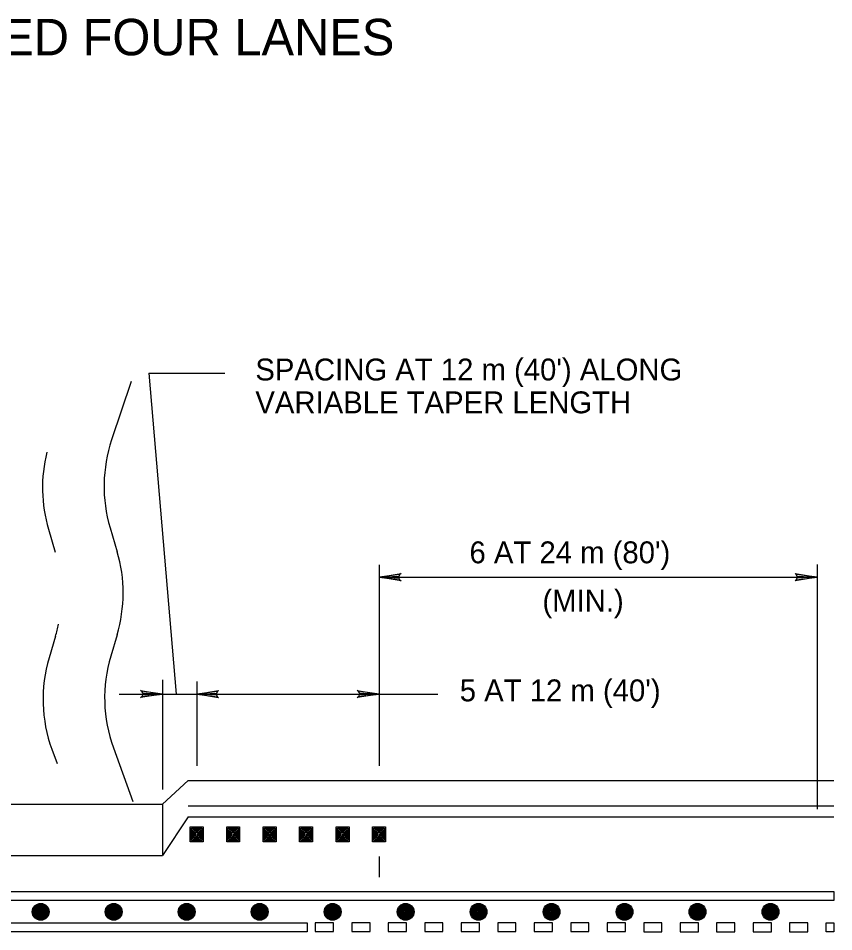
# Model space of a CAD drawing. Extents: x 639362 to 641108, y 298458 to 299646.
# Drawn here: x 640689.2 to 640800.9, y 299355.1 to 299480.3 of the extents above; entities that cross this region are included whole.
import ezdxf

# ---------------------------------------------------------------- set-up
doc = ezdxf.new("R2010")
doc.units = 0
doc.layers.add('2', color=7, linetype='Continuous')
doc.layers.add('3', color=7, linetype='Continuous')

# ---------------------------------------------------------------- blocks, each defined once
blk = doc.blocks.new('RARROW')
at = {"layer": '3'}
blk.add_lwpolyline([(-2.2695, 0.285), (-2.184875, 0.12075), (0, 0), (-2.2695, 0.285), (-2.38575, 0.384625), (0, 0), (-2.183125, -0.108), (-2.262875, -0.2705), (0, 0), (-2.38575, -0.379125), (-2.262875, -0.2705)], dxfattribs=at)

msp = doc.modelspace()

# ---------------------------------------------------------------- linework, layer by layer
at = {"layer": '2'}
for p, q in [((640707.1, 299431.65), (640710.82, 299387.69)), ((640707.1, 299431.65), (640717.52, 299431.65)), ((640704.67, 299430.52), (640701.99, 299422.54)), ((640693.33, 299410.27), (640694.26, 299407.14)), ((640701.77, 299410.48), (640702.75, 299407.2)), ((640738.64, 299405.38), (640738.64, 299377.85)), ((640798.64, 299405.43), (640798.64, 299371.92)), ((640738.64, 299403.7), (640798.64, 299403.7)), ((640702.74, 299395.81), (640701.86, 299392.88)), ((640694.3, 299395.6), (640693.42, 299392.66)), ((640708.95, 299389.65), (640708.95, 299374.61)), ((640713.64, 299389.43), (640713.64, 299377.85)), ((640703, 299387.69), (640713.64, 299387.69)), ((640713.64, 299387.69), (640746.68, 299387.69)), ((640693.79, 299380.12), (640694.51, 299378.15)), ((640702.24, 299380.33), (640704.91, 299372.97)), ((640712.47, 299375.85), (640708.95, 299372.61)), ((640712.47, 299375.85), (640800.93, 299375.85)), ((640671.45, 299372.61), (640708.95, 299372.61)), ((640708.95, 299372.61), (640708.95, 299365.58)), ((640712.47, 299372.35), (640800.93, 299372.35)), ((640712.47, 299370.85), (640708.95, 299365.58)), ((640712.47, 299370.85), (640800.93, 299370.85)), ((640712.75, 299369.47), (640714.53, 299369.47)), ((640712.75, 299367.43), (640712.75, 299369.47)), ((640714.53, 299369.47), (640714.53, 299367.43)), ((640717.75, 299369.47), (640719.53, 299369.47)), ((640717.75, 299367.43), (640717.75, 299369.47)), ((640719.53, 299369.47), (640719.53, 299367.43)), ((640722.75, 299369.47), (640724.53, 299369.47)), ((640722.75, 299367.43), (640722.75, 299369.47)), ((640724.53, 299369.47), (640724.53, 299367.43)), ((640727.75, 299369.47), (640729.53, 299369.47)), ((640727.75, 299367.43), (640727.75, 299369.47)), ((640729.53, 299369.47), (640729.53, 299367.43)), ((640732.75, 299369.47), (640734.53, 299369.47)), ((640732.75, 299367.43), (640732.75, 299369.47)), ((640734.53, 299369.47), (640734.53, 299367.43)), ((640737.75, 299369.47), (640739.53, 299369.47)), ((640737.75, 299367.43), (640737.75, 299369.47)), ((640739.53, 299369.47), (640739.53, 299367.43)), ((640712.93, 299369.29), (640714.35, 299369.29)), ((640712.93, 299367.61), (640712.93, 299369.29)), ((640713.11, 299369.12), (640714.17, 299369.12)), ((640713.11, 299367.79), (640713.11, 299369.12)), ((640713.28, 299367.96), (640713.28, 299368.94)), ((640713.28, 299368.94), (640713.99, 299368.94)), ((640713.46, 299368.76), (640713.82, 299368.76)), ((640713.46, 299368.14), (640713.46, 299368.76)), ((640713.82, 299368.14), (640713.46, 299368.14)), ((640713.64, 299368.59), (640713.64, 299368.32)), ((640713.82, 299368.76), (640713.82, 299368.14)), ((640713.99, 299368.94), (640713.99, 299367.96)), ((640714.17, 299369.12), (640714.17, 299367.79)), ((640714.35, 299369.29), (640714.35, 299367.61)), ((640717.93, 299369.29), (640719.35, 299369.29)), ((640717.93, 299367.61), (640717.93, 299369.29)), ((640718.11, 299369.11), (640719.17, 299369.11)), ((640718.11, 299367.79), (640718.11, 299369.11)), ((640718.28, 299367.96), (640718.28, 299368.94)), ((640718.28, 299368.94), (640718.99, 299368.94)), ((640718.46, 299368.76), (640718.82, 299368.76)), ((640718.46, 299368.14), (640718.46, 299368.76)), ((640718.82, 299368.14), (640718.46, 299368.14)), ((640718.64, 299368.59), (640718.64, 299368.32)), ((640718.82, 299368.76), (640718.82, 299368.14)), ((640718.99, 299368.94), (640718.99, 299367.96)), ((640719.17, 299369.11), (640719.17, 299367.79)), ((640719.35, 299369.29), (640719.35, 299367.61)), ((640722.93, 299369.29), (640724.35, 299369.29)), ((640722.93, 299367.61), (640722.93, 299369.29)), ((640723.11, 299369.11), (640724.17, 299369.11)), ((640723.11, 299367.79), (640723.11, 299369.11)), ((640723.28, 299367.96), (640723.28, 299368.94)), ((640723.28, 299368.94), (640723.99, 299368.94)), ((640723.46, 299368.76), (640723.82, 299368.76)), ((640723.46, 299368.14), (640723.46, 299368.76)), ((640723.82, 299368.14), (640723.46, 299368.14)), ((640723.64, 299368.58), (640723.64, 299368.32)), ((640723.82, 299368.76), (640723.82, 299368.14)), ((640723.99, 299368.94), (640723.99, 299367.96)), ((640724.17, 299369.11), (640724.17, 299367.79)), ((640724.35, 299369.29), (640724.35, 299367.61)), ((640727.93, 299369.29), (640729.35, 299369.29)), ((640727.93, 299367.61), (640727.93, 299369.29)), ((640728.11, 299369.11), (640729.17, 299369.11)), ((640728.11, 299367.78), (640728.11, 299369.11)), ((640728.28, 299367.96), (640728.28, 299368.94)), ((640728.28, 299368.94), (640728.99, 299368.94)), ((640728.46, 299368.76), (640728.82, 299368.76)), ((640728.46, 299368.14), (640728.46, 299368.76)), ((640728.64, 299368.58), (640728.64, 299368.31)), ((640728.82, 299368.76), (640728.82, 299368.14)), ((640728.99, 299368.94), (640728.99, 299367.96)), ((640729.17, 299369.11), (640729.17, 299367.78)), ((640729.35, 299369.29), (640729.35, 299367.61)), ((640732.93, 299369.29), (640734.35, 299369.29)), ((640732.93, 299367.6), (640732.93, 299369.29)), ((640733.11, 299369.11), (640734.17, 299369.11)), ((640733.11, 299367.78), (640733.11, 299369.11)), ((640733.28, 299367.96), (640733.28, 299368.93)), ((640733.28, 299368.93), (640733.99, 299368.93)), ((640733.46, 299368.76), (640733.82, 299368.76)), ((640733.46, 299368.14), (640733.46, 299368.76)), ((640733.64, 299368.58), (640733.64, 299368.31)), ((640733.82, 299368.76), (640733.82, 299368.14)), ((640733.99, 299368.93), (640733.99, 299367.96)), ((640734.17, 299369.11), (640734.17, 299367.78)), ((640734.35, 299369.29), (640734.35, 299367.6)), ((640737.93, 299369.29), (640739.35, 299369.29)), ((640737.93, 299367.6), (640737.93, 299369.29)), ((640738.11, 299369.11), (640739.17, 299369.11)), ((640738.11, 299367.78), (640738.11, 299369.11)), ((640738.28, 299367.96), (640738.28, 299368.93)), ((640738.28, 299368.93), (640738.99, 299368.93)), ((640738.46, 299368.76), (640738.82, 299368.76)), ((640738.46, 299368.14), (640738.46, 299368.76)), ((640738.64, 299368.58), (640738.64, 299368.31)), ((640738.82, 299368.76), (640738.82, 299368.14)), ((640738.99, 299368.93), (640738.99, 299367.96)), ((640739.17, 299369.11), (640739.17, 299367.78)), ((640739.35, 299369.29), (640739.35, 299367.6)), ((640714.53, 299367.43), (640712.75, 299367.43)), ((640714.35, 299367.61), (640712.93, 299367.61)), ((640714.17, 299367.79), (640713.11, 299367.79)), ((640713.99, 299367.96), (640713.28, 299367.96)), ((640719.53, 299367.43), (640717.75, 299367.43)), ((640719.35, 299367.61), (640717.93, 299367.61)), ((640719.17, 299367.79), (640718.11, 299367.79)), ((640718.99, 299367.96), (640718.28, 299367.96)), ((640724.53, 299367.43), (640722.75, 299367.43)), ((640724.35, 299367.61), (640722.93, 299367.61)), ((640724.17, 299367.79), (640723.11, 299367.79)), ((640723.99, 299367.96), (640723.28, 299367.96)), ((640729.53, 299367.43), (640727.75, 299367.43)), ((640729.35, 299367.61), (640727.93, 299367.61)), ((640729.17, 299367.78), (640728.11, 299367.78)), ((640728.99, 299367.96), (640728.28, 299367.96)), ((640728.82, 299368.14), (640728.46, 299368.14)), ((640734.53, 299367.43), (640732.75, 299367.43)), ((640734.35, 299367.6), (640732.93, 299367.6)), ((640734.17, 299367.78), (640733.11, 299367.78)), ((640733.99, 299367.96), (640733.28, 299367.96)), ((640733.82, 299368.14), (640733.46, 299368.14)), ((640739.53, 299367.43), (640737.75, 299367.43)), ((640739.35, 299367.6), (640737.93, 299367.6)), ((640739.17, 299367.78), (640738.11, 299367.78)), ((640738.99, 299367.96), (640738.28, 299367.96)), ((640738.82, 299368.14), (640738.46, 299368.14)), ((640671.45, 299365.58), (640708.95, 299365.58)), ((640738.64, 299365.43), (640738.64, 299362.61)), ((640652.18, 299360.61), (640800.93, 299360.61)), ((640800.93, 299359.41), (640652.18, 299359.41)), ((640800.93, 299360.61), (640800.93, 299359.41)), ((640577.73, 299356.31), (640728.77, 299356.31)), ((640728.77, 299356.31), (640728.77, 299355.11)), ((640729.89, 299356.33), (640729.89, 299355.13)), ((640732.39, 299356.33), (640729.89, 299356.33)), ((640732.39, 299355.13), (640732.39, 299356.33)), ((640734.89, 299356.33), (640734.89, 299355.13)), ((640737.39, 299356.33), (640734.89, 299356.33)), ((640737.39, 299355.13), (640737.39, 299356.33)), ((640739.89, 299356.32), (640739.89, 299355.12)), ((640742.39, 299356.32), (640739.89, 299356.32)), ((640742.39, 299355.12), (640742.39, 299356.32)), ((640744.89, 299356.32), (640744.89, 299355.12)), ((640747.39, 299356.32), (640744.89, 299356.32)), ((640747.39, 299355.12), (640747.39, 299356.32)), ((640749.89, 299356.32), (640749.89, 299355.12)), ((640752.39, 299356.32), (640749.89, 299356.32)), ((640752.39, 299355.12), (640752.39, 299356.32)), ((640754.89, 299356.32), (640754.89, 299355.12)), ((640757.39, 299356.32), (640754.89, 299356.32)), ((640757.39, 299355.12), (640757.39, 299356.32)), ((640759.89, 299356.32), (640759.89, 299355.12)), ((640762.39, 299356.32), (640759.89, 299356.32)), ((640762.39, 299355.12), (640762.39, 299356.32)), ((640764.89, 299356.32), (640764.89, 299355.12)), ((640767.39, 299356.32), (640764.89, 299356.32)), ((640767.39, 299355.12), (640767.39, 299356.32)), ((640769.89, 299356.32), (640769.89, 299355.12)), ((640772.39, 299356.32), (640769.89, 299356.32)), ((640772.39, 299355.12), (640772.39, 299356.32)), ((640774.89, 299356.32), (640774.89, 299355.11)), ((640777.39, 299356.32), (640774.89, 299356.32)), ((640777.39, 299355.11), (640777.39, 299356.32)), ((640779.89, 299356.31), (640779.89, 299355.11)), ((640782.39, 299356.31), (640779.89, 299356.31)), ((640782.39, 299355.11), (640782.39, 299356.31)), ((640784.89, 299356.31), (640784.89, 299355.11)), ((640787.39, 299356.31), (640784.89, 299356.31)), ((640787.39, 299355.11), (640787.39, 299356.31)), ((640789.89, 299356.31), (640789.89, 299355.11)), ((640792.39, 299356.31), (640789.89, 299356.31)), ((640792.39, 299355.11), (640792.39, 299356.31)), ((640794.89, 299356.31), (640794.89, 299355.11)), ((640797.39, 299356.31), (640794.89, 299356.31)), ((640797.39, 299355.11), (640797.39, 299356.31)), ((640799.89, 299355.11), (640799.89, 299356.31)), ((640799.89, 299356.31), (640800.93, 299356.31)), ((640800.93, 299356.31), (640800.93, 299355.11)), ((640728.77, 299355.11), (640577.73, 299355.11)), ((640729.89, 299355.13), (640732.39, 299355.13)), ((640734.89, 299355.12), (640737.39, 299355.12)), ((640739.89, 299355.12), (640742.39, 299355.12)), ((640744.89, 299355.12), (640747.39, 299355.12)), ((640749.89, 299355.12), (640752.39, 299355.12)), ((640754.89, 299355.12), (640757.39, 299355.12)), ((640759.89, 299355.12), (640762.39, 299355.12)), ((640764.89, 299355.12), (640767.39, 299355.12)), ((640769.89, 299355.12), (640772.39, 299355.12)), ((640774.89, 299355.11), (640777.39, 299355.11)), ((640779.89, 299355.11), (640782.39, 299355.11)), ((640784.89, 299355.11), (640787.39, 299355.11)), ((640789.89, 299355.11), (640792.39, 299355.11)), ((640794.89, 299355.11), (640797.39, 299355.11)), ((640800.93, 299355.11), (640799.89, 299355.11)), ((640799.89, 299355.11), (640799.89, 299355.11))]:
    msp.add_line(p, q, dxfattribs=at)
for centre, radius in [((640692.27, 299357.84), 1.15), ((640692.27, 299357.84), 1.07), ((640692.27, 299357.84), 0.985), ((640692.27, 299357.84), 0.904), ((640692.27, 299357.84), 0.822), ((640692.27, 299357.84), 0.741), ((640692.27, 299357.84), 0.659), ((640692.27, 299357.84), 0.578), ((640692.27, 299357.84), 0.496), ((640692.27, 299357.84), 0.414), ((640692.27, 299357.84), 0.333), ((640702.27, 299357.84), 1.15), ((640702.27, 299357.84), 1.07), ((640702.27, 299357.84), 0.985), ((640702.27, 299357.84), 0.904), ((640702.27, 299357.84), 0.822), ((640702.27, 299357.84), 0.741), ((640702.27, 299357.84), 0.659), ((640702.27, 299357.84), 0.578), ((640702.27, 299357.84), 0.496), ((640702.27, 299357.84), 0.414), ((640702.27, 299357.84), 0.333), ((640712.27, 299357.83), 1.15), ((640712.27, 299357.83), 1.07), ((640712.27, 299357.83), 0.985), ((640712.27, 299357.83), 0.904), ((640712.27, 299357.83), 0.822), ((640712.27, 299357.83), 0.741), ((640712.27, 299357.83), 0.659), ((640712.27, 299357.83), 0.578), ((640712.27, 299357.83), 0.496), ((640712.27, 299357.83), 0.414), ((640712.27, 299357.83), 0.333), ((640722.27, 299357.83), 1.15), ((640722.27, 299357.83), 1.07), ((640722.27, 299357.83), 0.985), ((640722.27, 299357.83), 0.904), ((640722.27, 299357.83), 0.822), ((640722.27, 299357.83), 0.741), ((640722.27, 299357.83), 0.659), ((640722.27, 299357.83), 0.578), ((640722.27, 299357.83), 0.496), ((640722.27, 299357.83), 0.414), ((640722.27, 299357.83), 0.333), ((640732.27, 299357.83), 1.15), ((640732.27, 299357.83), 1.07), ((640732.27, 299357.83), 0.985), ((640732.27, 299357.83), 0.904), ((640732.27, 299357.83), 0.822), ((640732.27, 299357.83), 0.741), ((640732.27, 299357.83), 0.659), ((640732.27, 299357.83), 0.578), ((640732.27, 299357.83), 0.496), ((640732.27, 299357.83), 0.414), ((640732.27, 299357.83), 0.333), ((640742.27, 299357.83), 1.15), ((640742.27, 299357.83), 1.07), ((640742.27, 299357.83), 0.985), ((640742.27, 299357.83), 0.904), ((640742.27, 299357.83), 0.822), ((640742.27, 299357.83), 0.741), ((640742.27, 299357.83), 0.659), ((640742.27, 299357.83), 0.578), ((640742.27, 299357.83), 0.496), ((640742.27, 299357.83), 0.414), ((640742.27, 299357.83), 0.333), ((640752.27, 299357.83), 1.15), ((640752.27, 299357.83), 1.07), ((640752.27, 299357.83), 0.985), ((640752.27, 299357.83), 0.904), ((640752.27, 299357.83), 0.822), ((640752.27, 299357.83), 0.741), ((640752.27, 299357.83), 0.659), ((640752.27, 299357.83), 0.578), ((640752.27, 299357.83), 0.496), ((640752.27, 299357.83), 0.414), ((640752.27, 299357.83), 0.333), ((640762.27, 299357.83), 1.15), ((640762.27, 299357.83), 1.07), ((640762.27, 299357.83), 0.985), ((640762.27, 299357.83), 0.904), ((640762.27, 299357.83), 0.822), ((640762.27, 299357.83), 0.741), ((640762.27, 299357.83), 0.659), ((640762.27, 299357.83), 0.578), ((640762.27, 299357.83), 0.496), ((640762.27, 299357.83), 0.414), ((640762.27, 299357.83), 0.333), ((640772.27, 299357.83), 1.15), ((640772.27, 299357.83), 1.07), ((640772.27, 299357.83), 0.985), ((640772.27, 299357.83), 0.904), ((640772.27, 299357.83), 0.822), ((640772.27, 299357.83), 0.741), ((640772.27, 299357.83), 0.659), ((640772.27, 299357.83), 0.578), ((640772.27, 299357.83), 0.496), ((640772.27, 299357.83), 0.414), ((640772.27, 299357.83), 0.333), ((640782.27, 299357.83), 1.15), ((640782.27, 299357.83), 1.07), ((640782.27, 299357.83), 0.985), ((640782.27, 299357.83), 0.904), ((640782.27, 299357.83), 0.822), ((640782.27, 299357.83), 0.741), ((640782.27, 299357.83), 0.659), ((640782.27, 299357.83), 0.578), ((640782.27, 299357.83), 0.496), ((640782.27, 299357.83), 0.414), ((640782.27, 299357.83), 0.333), ((640792.27, 299357.83), 1.15), ((640792.27, 299357.83), 1.07), ((640792.27, 299357.83), 0.985), ((640792.27, 299357.83), 0.904), ((640792.27, 299357.83), 0.822), ((640792.27, 299357.83), 0.741), ((640792.27, 299357.83), 0.659), ((640792.27, 299357.83), 0.578), ((640792.27, 299357.83), 0.496), ((640792.27, 299357.83), 0.414), ((640792.27, 299357.83), 0.333), ((640692.27, 299357.84), 0.251), ((640692.27, 299357.84), 0.17), ((640692.27, 299357.84), 0.0881), ((640702.27, 299357.84), 0.251), ((640702.27, 299357.84), 0.17), ((640702.27, 299357.84), 0.0881), ((640712.27, 299357.83), 0.251), ((640712.27, 299357.83), 0.17), ((640712.27, 299357.83), 0.0881), ((640722.27, 299357.83), 0.251), ((640722.27, 299357.83), 0.17), ((640722.27, 299357.83), 0.0881), ((640732.27, 299357.83), 0.251), ((640732.27, 299357.83), 0.17), ((640732.27, 299357.83), 0.0881), ((640742.27, 299357.83), 0.251), ((640742.27, 299357.83), 0.17), ((640742.27, 299357.83), 0.0881), ((640752.27, 299357.83), 0.251), ((640752.27, 299357.83), 0.17), ((640752.27, 299357.83), 0.0881), ((640762.27, 299357.83), 0.251), ((640762.27, 299357.83), 0.17), ((640762.27, 299357.83), 0.0881), ((640772.27, 299357.83), 0.251), ((640772.27, 299357.83), 0.17), ((640772.27, 299357.83), 0.0881), ((640782.27, 299357.83), 0.251), ((640782.27, 299357.83), 0.17), ((640782.27, 299357.83), 0.0881), ((640792.27, 299357.83), 0.251), ((640792.27, 299357.83), 0.17), ((640792.27, 299357.83), 0.0881)]:
    msp.add_circle(centre, radius, dxfattribs=at)
for centre, start, end in [((640720.95, 299416.16), 161.4259, 196.5084), ((640712.51, 299415.95), 165.8785, 196.5084), ((640683.57, 299401.52), 343.4142, 16.5084), ((640675.13, 299401.31), 343.4142, 348.3347), ((640712.59, 299386.95), 163.4142, 199.9879), ((640721.03, 299387.17), 163.4142, 199.9879)]:
    msp.add_arc(centre, 20, start, end, dxfattribs=at)

# ---------------------------------------------------------------- block references
at = {"layer": '2', "xscale": 1.2574347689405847, "yscale": 1.3092961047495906, "rotation": 180}
for p in [(640738.64, 299403.7), (640713.64, 299387.69)]:
    msp.add_blockref('RARROW', p, dxfattribs=at)
at = {"layer": '2', "xscale": 1.2574347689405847, "yscale": 1.3092961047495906}
for p in [(640798.64, 299403.7), (640708.95, 299387.69), (640738.64, 299387.69)]:
    msp.add_blockref('RARROW', p, dxfattribs=at)

# ---------------------------------------------------------------- texts
at = {"layer": '2'}
for s, height, p in [('UNDIVIDED FOUR LANES', 5, (640659.37, 299475.24)), ("SPACING AT 12 m (40') ALONG", 3, (640721.68, 299430.67)), ('VARIABLE TAPER LENGTH', 3, (640721.68, 299426.17)), ("6 AT 24 m (80')", 3, (640751.02, 299405.61)), (' (MIN.)', 3, (640759.9, 299398.99)), ("5 AT 12 m (40')", 3, (640749.69, 299386.69))]:
    msp.add_text(s, height=height, dxfattribs=at).set_placement(p)

doc.saveas('drawing.dxf')
